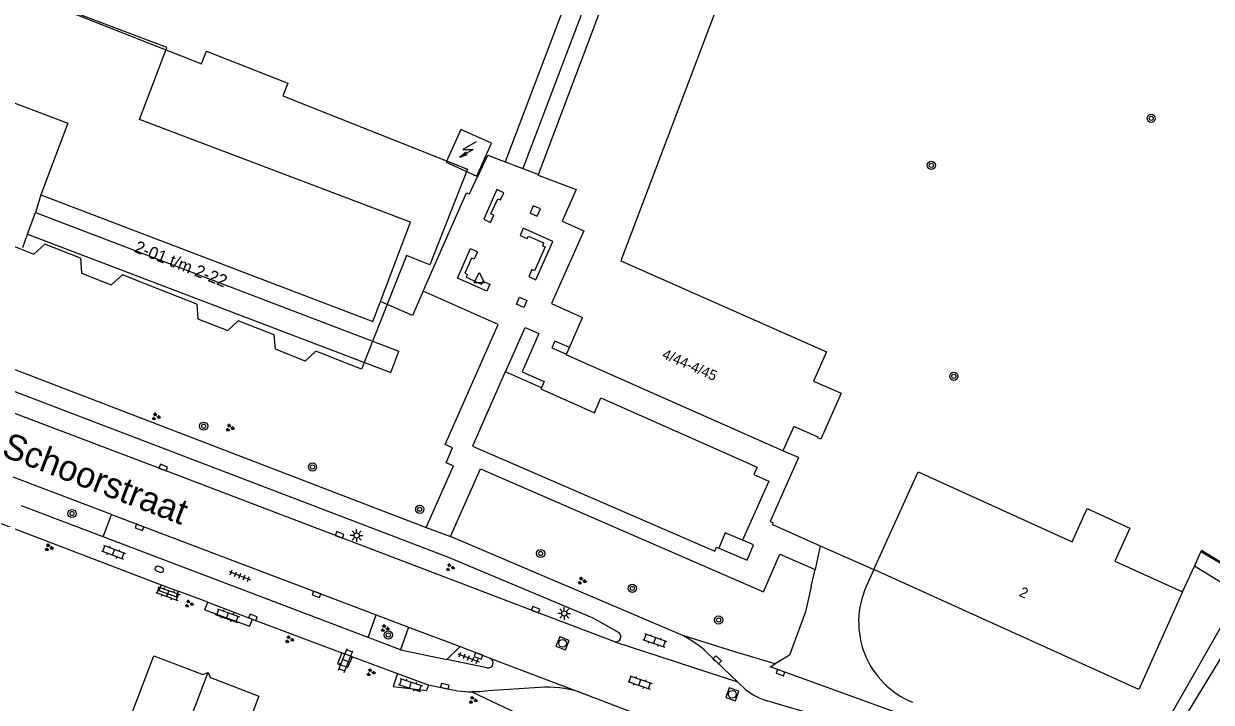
# Model space of a CAD drawing. Extents: x 136000 to 141014, y 402000 to 403500.
# Drawn here: x 137842.2 to 137958.3, y 402614.1 to 402680.4 of the extents above; entities that cross this region are included whole.
import ezdxf

# ---------------------------------------------------------------- set-up
doc = ezdxf.new("R2010")
doc.units = 0
for name, color, linetype in [('gg-afsc-hekwerk', 7, 'Continuous'), ('gg-afsc-muur', 7, 'Continuous'), ('gg-anno-huisnummerreeks BGT', 7, 'Continuous'), ('gg-anno-openbare ruimte label', 7, 'Continuous'), ('gg-bbg-bijgebouw', 7, 'Continuous'), ('gg-bbg-hoofdgebouw', 7, 'Continuous'), ('gg-bbg-lage trafo', 7, 'Continuous'), ('gg-bbg-tussenscheiding', 7, 'Continuous'), ('gg-knt-verharding', 7, 'Continuous'), ('gg-knt-verharding nz', 7, 'Continuous'), ('gt-anno-plantopografie huisnummer', 7, 'Continuous'), ('gt-bbg-plantopografie pand', 7, 'Continuous'), ('gt-grn-vlakafsluiter', 7, 'Continuous'), ('gt-grn-weggrens', 7, 'Continuous'), ('gt-symb-boom', 7, 'Continuous'), ('gt-symb-brandkraan', 7, 'Continuous'), ('gt-symb-groenvak', 7, 'Continuous'), ('gt-symb-klinker verharding', 7, 'Continuous'), ('gt-symb-kolk', 7, 'Continuous'), ('gt-symb-lichtmast', 7, 'Continuous'), ('gt-symb-rioolschacht', 7, 'Continuous'), ('gt-symb-tegel verharding', 7, 'Continuous'), ('gt-symb-trafo symbool', 7, 'Continuous'), ('gt-symb-waterafsluiter', 7, 'Continuous')]:
    doc.layers.add(name, color=color, linetype=linetype)

# ---------------------------------------------------------------- blocks, each defined once
blk = doc.blocks.new('gt0-BOOM')
at = {"layer": 'gt-symb-boom'}
for radius in [0.4, 0.2]:
    blk.add_circle((0, 0), radius, dxfattribs=at)
blk = doc.blocks.new('gt0-HSP')
at = {"layer": 'gt-symb-trafo symbool'}
for points in [[(0.77, 0.75), (-0.53, 0), (0.47, 0), (-0.83, -0.75)], [(-0.22, -0.24), (-0.83, -0.75), (-0.08, -0.48)]]:
    blk.add_lwpolyline(points, dxfattribs=at)
blk = doc.blocks.new('gt0-WAFSL')
at = {"layer": 'gt-symb-waterafsluiter'}
for p, q in [((-0.5, -0.33), (0, 0.67)), ((0, 0.67), (0.5, -0.33)), ((0.5, -0.33), (-0.5, -0.33))]:
    blk.add_line(p, q, dxfattribs=at)
blk = doc.blocks.new('gt0-KOLK')
at = {"layer": 'gt-symb-kolk'}
blk.add_lwpolyline([(0, 0), (0.38, 0), (0.38, 0.4), (-0.37, 0.4), (-0.37, 0), (0, 0)], dxfattribs=at)
blk = doc.blocks.new('gt0-GRVAK')
at = {"layer": 'gt-symb-groenvak'}
for p, q in [((-0.11, 0.19), (-0.23, 0.24)), ((-0.18, 0.15), (0.09, 0.15)), ((-0.09, 0.21), (-0.16, 0.32)), ((-0.05, 0.21), (-0.05, 0.39)), ((0, 0.21), (0.06, 0.32)), ((0.02, 0.19), (0.13, 0.24)), ((0.26, -0.05), (0.2, 0.06)), ((0.31, -0.05), (0.31, 0.13)), ((0.35, -0.05), (0.41, 0.06)), ((-0.24, -0.23), (-0.36, -0.18)), ((-0.32, -0.26), (-0.05, -0.26)), ((-0.23, -0.21), (-0.29, -0.1)), ((-0.18, -0.2), (-0.18, -0.02)), ((-0.14, -0.21), (-0.07, -0.1)), ((-0.12, -0.23), (0, -0.18)), ((0.24, -0.07), (0.12, -0.02)), ((0.17, -0.11), (0.44, -0.11)), ((0.37, -0.07), (0.49, -0.02))]:
    blk.add_line(p, q, dxfattribs=at)
blk = doc.blocks.new('gt0-KL1')
at = {"layer": 'gt-symb-klinker verharding'}
for p, q in [((-1.15, 0.3), (1.15, 0.3)), ((-1, -0.3), (-1, 0.3)), ((-0.5, 0.3), (-0.5, 0.45)), ((0, -0.3), (0, 0.3)), ((0.5, 0.3), (0.5, 0.45)), ((1, -0.3), (1, 0.3)), ((-1.15, -0.3), (1.15, -0.3)), ((-0.5, -0.45), (-0.5, -0.3)), ((0.5, -0.45), (0.5, -0.3))]:
    blk.add_line(p, q, dxfattribs=at)
blk = doc.blocks.new('gt0-TEG1')
at = {"layer": 'gt-symb-tegel verharding'}
for p, q in [((-1.12, 0), (1.12, 0)), ((-0.9, -0.25), (-0.9, 0.25)), ((-0.45, -0.25), (-0.45, 0.25)), ((0, -0.25), (0, 0.25)), ((0.45, -0.25), (0.45, 0.25)), ((0.9, -0.25), (0.9, 0.25))]:
    blk.add_line(p, q, dxfattribs=at)
blk = doc.blocks.new('gt0-BR')
at = {"layer": 'gt-symb-brandkraan'}
for centre, radius, start, end in [((-0.24, 0), 0.206, 107.5669, 252.4331), ((0.6, -2.66), 3, 106.892, 107.5669), ((0, -0.69), 0.938, 73.108, 106.892), ((-0.6, -2.66), 3, 72.4331, 73.108), ((0.24, 0), 0.206, 287.567, 72.4331), ((0.6, 2.66), 3, 252.4331, 253.108), ((0, 0.69), 0.938, 253.108, 286.8921), ((-0.6, 2.66), 3, 286.8921, 287.567)]:
    blk.add_arc(centre, radius, start, end, dxfattribs=at)
blk = doc.blocks.new('gt0-LMAST')
at = {"layer": 'gt-symb-lichtmast'}
for p, q in [((-0.18, 0.17), (-0.45, 0.44)), ((0, 0.25), (0, 0.62)), ((0.17, 0.17), (0.44, 0.44)), ((-0.25, 0), (-0.63, 0)), ((-0.18, -0.18), (-0.45, -0.45)), ((0, -0.25), (0, -0.63)), ((0.44, -0.45), (0.17, -0.18)), ((0.25, 0), (0.62, 0))]:
    blk.add_line(p, q, dxfattribs=at)
blk.add_circle((0, 0), 0.25, dxfattribs=at)
blk = doc.blocks.new('gt0-RS')
at = {"layer": 'gt-symb-rioolschacht'}
blk.add_lwpolyline([(-0.5, -0.5), (0.5, -0.5), (0.5, 0.5), (-0.5, 0.5)], close=True, dxfattribs=at)
blk.add_circle((0, 0), 0.375, dxfattribs=at)

msp = doc.modelspace()

# ---------------------------------------------------------------- linework, layer by layer
at = {"layer": 'gg-afsc-hekwerk'}
msp.add_lwpolyline([(137990.44, 402673.96), (137961.64, 402626.3), (137957.37, 402628.91)], dxfattribs=at)
at = {"layer": 'gg-afsc-muur'}
for p, q in [((137956.68, 402627.39), (137957.32, 402628.79)), ((137957.32, 402628.79), (137957.37, 402628.91)), ((137955.53, 402624.86), (137956.68, 402627.39)), ((137961.1, 402624.65), (137956.68, 402627.39)), ((137925.35, 402627.04), (137924.61, 402625.39)), ((137951.84, 402608.46), (137961.1, 402624.65))]:
    msp.add_line(p, q, dxfattribs=at)
msp.add_arc((137932.31, 402621.92), 8.45, 155.7292, 247.9261, dxfattribs=at)
at = {"layer": 'gg-bbg-bijgebouw'}
for points in [[(137883.55, 402666.85), (137886.53, 402665.49), (137887.98, 402668.7), (137884.99, 402670.06), (137883.55, 402666.85)], [(137851.53, 402609.67), (137854.97, 402618.63), (137859.75, 402616.79), (137860.25, 402617)]]:
    msp.add_lwpolyline(points, dxfattribs=at)
at = {"layer": 'gg-bbg-hoofdgebouw'}
for p, q in [((137892.52, 402665.59), (137892.55, 402665.66)), ((137892.52, 402665.59), (137896.25, 402664.17)), ((137877.11, 402653.24), (137880.07, 402660.99)), ((137894.56, 402652.71), (137896.88, 402651.68)), ((137895.59, 402648.76), (137896.88, 402651.68)), ((137895.29, 402648.1), (137895.59, 402648.76))]:
    msp.add_line(p, q, dxfattribs=at)
for points in [[(137880.07, 402660.99), (137853.57, 402671.03), (137856.23, 402678.07), (137826.9, 402689.16), (137829.55, 402696.12), (137795.48, 402709.08), (137795.68, 402709.6), (137795.05, 402709.83), (137805.34, 402737.17)], [(137711.67, 402729.74), (137739.8, 402719), (137739.15, 402717.27), (137742.62, 402715.96), (137743.27, 402717.69), (137760.01, 402711.34), (137759.35, 402709.61), (137762.3, 402708.49), (137760.48, 402703.76), (137765.7, 402701.8), (137767.41, 402706.54), (137770.41, 402705.43), (137771.06, 402707.16), (137787.83, 402700.83), (137787.16, 402699.11), (137790.63, 402697.76), (137791.29, 402699.49), (137820.04, 402688.72), (137817.37, 402681.71), (137846.57, 402670.68), (137843.91, 402663.65)], [(137892.55, 402665.66), (137900.7, 402687.29), (137903.14, 402686.37), (137903.99, 402688.68), (137908.52, 402686.96), (137907.65, 402684.66), (137910.58, 402683.55)], [(137910.58, 402683.55), (137900.63, 402657.21), (137920.73, 402648.31)], [(137843.91, 402663.65), (137876.38, 402651.3), (137877.11, 402653.24)], [(137896.25, 402664.17), (137894.89, 402661.1), (137895.12, 402660.99)], [(137895.12, 402660.99), (137897, 402660.16), (137893.83, 402653.03), (137894.56, 402652.71)], [(137920.73, 402648.31), (137919.46, 402645.45), (137922.14, 402644.27), (137920.16, 402639.78), (137919.86, 402639.91), (137919.89, 402639.99), (137917.51, 402641.04), (137916.46, 402638.66)], [(137916.46, 402638.66), (137895.26, 402648.03), (137895.29, 402648.1)], [(137925.35, 402627.04), (137929.69, 402636.6), (137944.72, 402629.77), (137946.19, 402633), (137950.38, 402631.1), (137948.91, 402627.87), (137955.53, 402624.86)], [(137955.53, 402624.86), (137951.24, 402615.33), (137925.35, 402627.04)], [(137860.25, 402617), (137860.49, 402616.5), (137865.24, 402614.67), (137864.12, 402611.75), (137866.39, 402610.92)]]:
    msp.add_lwpolyline(points, dxfattribs=at)
at = {"layer": 'gg-bbg-lage trafo'}
for points in [[(137912.51, 402629.91), (137910.81, 402630.63), (137910.19, 402629.15)], [(137910.19, 402629.15), (137912.95, 402627.98), (137913.57, 402629.47), (137912.51, 402629.91)]]:
    msp.add_lwpolyline(points, dxfattribs=at)
at = {"layer": 'gg-bbg-tussenscheiding'}
msp.add_line((137860.25, 402617), (137856.69, 402607.69), dxfattribs=at)
at = {"layer": 'gg-knt-verharding'}
for p, q in [((137891.02, 402666.24), (137892.55, 402665.66)), ((137843.91, 402663.65), (137843.39, 402661.92)), ((137843.39, 402661.92), (137878.92, 402648.4)), ((137842.17, 402658.53), (137842.62, 402659.82)), ((137842.62, 402659.82), (137878.12, 402646.3)), ((137815.26, 402656.59), (137881.6, 402631.17)), ((137878.12, 402646.3), (137878.92, 402648.4)), ((137892.86, 402644.82), (137889.34, 402646.36)), ((137850.83, 402632.44), (137841.23, 402636.08)), ((137830.26, 402635.26), (137855.69, 402625.57)), ((137850.01, 402630.25), (137842.03, 402633.27)), ((137850.01, 402630.25), (137850.83, 402632.44)), ((137850.83, 402632.44), (137876.71, 402622.62)), ((137915.43, 402631.45), (137920.11, 402629.37)), ((137875.92, 402620.4), (137850.01, 402630.25)), ((137906.69, 402620.61), (137883.98, 402630.28)), ((137920.11, 402629.37), (137925.35, 402627.04)), ((137963.37, 402625.22), (137957.32, 402628.79)), ((137919.22, 402625.38), (137919.6, 402627.06)), ((137855.69, 402625.57), (137855.46, 402625)), ((137855.69, 402625.57), (137857.34, 402624.93)), ((137857.34, 402624.93), (137857.14, 402624.37)), ((137860.23, 402623.85), (137857.34, 402624.93)), ((137859.96, 402623.1), (137860.23, 402623.85)), ((137860.23, 402623.85), (137864.57, 402622.19)), ((137864.57, 402622.19), (137864.32, 402621.52)), ((137864.57, 402622.19), (137873.33, 402618.92)), ((137875.92, 402620.4), (137876.71, 402622.62)), ((137876.71, 402622.62), (137879.87, 402621.43)), ((137879.09, 402619.22), (137875.92, 402620.4)), ((137879.87, 402621.43), (137879.09, 402619.22)), ((137879.87, 402621.43), (137884.92, 402619.52)), ((137883.59, 402618.26), (137884.92, 402619.52)), ((137873.33, 402618.92), (137872.93, 402617.83)), ((137874.39, 402618.51), (137873.33, 402618.92)), ((137873.93, 402617.51), (137874.39, 402618.51)), ((137874.39, 402618.51), (137878.77, 402616.88)), ((137887.53, 402617.45), (137883.59, 402618.26)), ((137912.01, 402616.09), (137909.89, 402618.09)), ((137878.77, 402616.88), (137878.35, 402615.61)), ((137881.82, 402615.8), (137881.61, 402615.24)), ((137881.82, 402615.8), (137883.36, 402615.46)), ((137912.83, 402615.31), (137912.01, 402616.09)), ((137886.05, 402615.1), (137893.99, 402611.35))]:
    msp.add_line(p, q, dxfattribs=at)
for points in [[(137919.05, 402718.8), (137909.2, 402707.35), (137894.26, 402696.18), (137892.52, 402695.8), (137894.83, 402681.39), (137889.3, 402666.9)], [(137920.71, 402717.75), (137910.61, 402706.15), (137895.75, 402694.91), (137894.79, 402693.56), (137896.71, 402681.16), (137891.02, 402666.24)], [(137881.29, 402654.25), (137885.52, 402663.87), (137885.82, 402663.76), (137886.6, 402665.46), (137886.65, 402665.44), (137887.62, 402667.54), (137889.3, 402666.9)], [(137889.18, 402663.86), (137888.49, 402664.18), (137887.21, 402661.27), (137887.88, 402660.97), (137888.2, 402661.67), (137887.92, 402661.8), (137888.6, 402663.27), (137888.86, 402663.18), (137889.18, 402663.86)], [(137892.06, 402662.59), (137891.75, 402661.88), (137892.45, 402661.57), (137892.77, 402662.28), (137892.06, 402662.59)], [(137891.08, 402660.39), (137890.76, 402659.69), (137891.46, 402659.38), (137891.59, 402659.64), (137893.07, 402658.96), (137892.97, 402658.69), (137893.23, 402658.57), (137892.19, 402656.25), (137891.92, 402656.38), (137891.61, 402655.67), (137892.32, 402655.37), (137893.97, 402659.09), (137891.08, 402660.39)], [(137887.82, 402654.92), (137887.52, 402654.24), (137884.64, 402655.51), (137885.93, 402658.41), (137886.61, 402658.09), (137886.28, 402657.39), (137886.03, 402657.49), (137885.38, 402656.01), (137885.63, 402655.89), (137885.5, 402655.63), (137887.01, 402654.95), (137887.14, 402655.22), (137887.82, 402654.92)], [(137881.6, 402631.17), (137884.25, 402637.18), (137883.53, 402637.48), (137884.16, 402638.95), (137883.44, 402639.26), (137888.61, 402650.98), (137881.29, 402654.25)], [(137890.71, 402653.65), (137891.41, 402653.33), (137891.12, 402652.64), (137890.41, 402652.97), (137890.71, 402653.65)], [(137900.45, 402620.88), (137897.9, 402622.3), (137883.7, 402628.26), (137824.65, 402650.8)], [(137889.34, 402646.36), (137891.26, 402650.69), (137892.6, 402650.1), (137890.96, 402646.38), (137893.12, 402645.42), (137892.86, 402644.82)], [(137895.59, 402648.76), (137894.16, 402649.36), (137893.88, 402648.72), (137895.29, 402648.1)], [(137900.02, 402620), (137892.21, 402622.95), (137855.81, 402636.83), (137835.67, 402644.45), (137829.85, 402646.72)], [(137889.34, 402646.36), (137889.32, 402646.37), (137886.13, 402639.11), (137909.81, 402628.86), (137909.97, 402629.24), (137910.19, 402629.15)], [(137892.86, 402644.82), (137892.81, 402644.72), (137898.05, 402642.36), (137898.67, 402643.83), (137913.93, 402637.07), (137913.62, 402636.35), (137915.07, 402635.7), (137912.51, 402629.91)], [(137917.98, 402637.99), (137915.22, 402631.74), (137915.48, 402631.64), (137915.43, 402631.45)], [(137883.98, 402630.28), (137886.91, 402636.9), (137914.57, 402624.89), (137916.17, 402628.54), (137919.6, 402627.06)], [(137919.22, 402625.38), (137918.67, 402622.93), (137917.11, 402618.68), (137915.71, 402617.85)], [(137951.84, 402608.46), (137953.62, 402609.1), (137962.53, 402623.75)], [(137915.71, 402617.85), (137911.77, 402619.02), (137906.69, 402620.61)], [(137884.92, 402619.52), (137886.77, 402618.81), (137887.82, 402618.39)], [(137928.6, 402612.69), (137915.22, 402617.55), (137915.71, 402617.85)], [(137878.77, 402616.88), (137881.53, 402615.87), (137881.82, 402615.8)], [(137892.65, 402615.53), (137887.65, 402615.19), (137886.85, 402615.11), (137886.05, 402615.1)], [(137896.52, 402615.1), (137924.24, 402604.56), (137929.77, 402602.38), (137934.4, 402600.36)], [(137937.54, 402607.39), (137920.47, 402612.58), (137914.9, 402614.24)]]:
    msp.add_lwpolyline(points, dxfattribs=at)
for centre, radius, start, end in [((137900.13, 402620.49), 0.502, 257.6436, 51.0617), ((137900.84, 402609.89), 12.21, 42.1908, 61.4031), ((137887.64, 402617.93), 0.497, 257.5264, 68.5656), ((137886.34, 402627.35), 12.25, 255.9308, 268.6228), ((137893.5, 402605.34), 10.22, 72.7687, 94.7264), ((137916.74, 402620.35), 6.38, 232.1812, 253.2605)]:
    msp.add_arc(centre, radius, start, end, dxfattribs=at)
at = {"layer": 'gg-knt-verharding nz'}
for p, q in [((137881.6, 402631.17), (137883.98, 402630.28)), ((137900.02, 402620), (137912.01, 402616.09)), ((137887.82, 402618.39), (137896.52, 402615.1))]:
    msp.add_line(p, q, dxfattribs=at)
at = {"layer": 'gt-bbg-plantopografie pand'}
for p, q in [((137847.79, 402657.47), (137844.32, 402658.84)), ((137855.53, 402654.41), (137851.9, 402655.84)), ((137859.16, 402652.97), (137855.53, 402654.41))]:
    msp.add_line(p, q, dxfattribs=at)
for points in [[(137841.56, 402683.61), (137859.63, 402676.46), (137860.12, 402677.71), (137868.06, 402674.57), (137867.56, 402673.32), (137885.64, 402666.16), (137881.94, 402656.82), (137879.65, 402657.72), (137875.26, 402646.62), (137870.79, 402648.4), (137869.76, 402647.42), (137866.85, 402648.58), (137866.74, 402649.97), (137863.22, 402651.36)], [(137840.2, 402660.48), (137840.31, 402659.03), (137843.23, 402657.87), (137844.32, 402658.84)], [(137847.79, 402657.47), (137847.89, 402656.02), (137850.81, 402654.86), (137851.9, 402655.84)], [(137859.16, 402652.97), (137859.27, 402651.56), (137862.2, 402650.4), (137863.22, 402651.36)]]:
    msp.add_lwpolyline(points, dxfattribs=at)
at = {"layer": 'gt-grn-vlakafsluiter'}
for p, q in [((137917.98, 402637.99), (137916.46, 402638.66)), ((137855.46, 402625), (137857.14, 402624.37)), ((137859.96, 402623.1), (137864.32, 402621.52)), ((137872.93, 402617.83), (137873.93, 402617.51)), ((137878.35, 402615.61), (137881.61, 402615.24))]:
    msp.add_line(p, q, dxfattribs=at)
msp.add_lwpolyline([(137881.29, 402654.25), (137880.24, 402651.86), (137877.11, 402653.24)], dxfattribs=at)
at = {"layer": 'gt-grn-weggrens'}
for p, q in [((137889.3, 402666.9), (137891.02, 402666.24)), ((137842.62, 402659.82), (137843.39, 402661.92)), ((137920.11, 402629.37), (137919.6, 402627.06)), ((137879.09, 402619.22), (137883.59, 402618.26))]:
    msp.add_line(p, q, dxfattribs=at)

# ---------------------------------------------------------------- block references
at = {"layer": 'gt-symb-boom'}
for p in [(137952.46, 402671.14), (137930.97, 402666.54), (137933.17, 402645.93), (137859.83, 402641.06), (137870.47, 402637.07), (137880.96, 402632.94), (137846.96, 402632.53), (137892.78, 402628.62), (137901.74, 402625.21), (137910.17, 402622.12), (137877.89, 402620.66)]:
    msp.add_blockref('gt0-BOOM', p, dxfattribs=at)
at = {"layer": 'gt-symb-brandkraan', "rotation": -19.70395158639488}
msp.add_blockref('gt0-BR', (137855.5, 402627.08), dxfattribs=at)
at = {"layer": 'gt-symb-groenvak'}
for p in [(137855.15, 402641.99), (137862.39, 402640.89), (137844.69, 402629.2), (137883.91, 402627.25), (137896.79, 402625.94), (137858.4, 402623.7), (137877.53, 402621.31), (137868.2, 402620.22), (137876.16, 402617), (137886.14, 402614.29)]:
    msp.add_blockref('gt0-GRVAK', p, dxfattribs=at)
at = {"layer": 'gt-symb-klinker verharding'}
for p, rotation in [((137851.02, 402628.74), -20.60969293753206), ((137856.34, 402624.7), -19.576725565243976), ((137862.16, 402622.55), -19.576725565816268), ((137903.93, 402620.13), -19.21431186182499), ((137873.72, 402618.16), 68.028289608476), ((137880.04, 402615.76), -17.945563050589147), ((137902.48, 402616.02), -19.21431186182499)]:
    msp.add_blockref('gt0-KL1', p, dxfattribs=dict(at, rotation=rotation))
at = {"layer": 'gt-symb-kolk'}
for p, rotation in [((137855.81, 402636.83), -20.737148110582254), ((137853.64, 402631.37), 159.2092747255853), ((137873.05, 402630.25), -20.91820498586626), ((137870.94, 402624.81), 159.2092747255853), ((137892.21, 402622.95), -20.844264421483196), ((137864.57, 402622.19), -20.918204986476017), ((137886.77, 402618.81), 159.26285188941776), ((137909.89, 402618.09), -43.3164899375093), ((137916.15, 402616.79), -19.630702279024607), ((137883.36, 402615.46), -13.01457605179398)]:
    msp.add_blockref('gt0-KOLK', p, dxfattribs=dict(at, rotation=rotation))
at = {"layer": 'gt-symb-lichtmast'}
for p in [(137874.79, 402630.38), (137895.09, 402622.76)]:
    msp.add_blockref('gt0-LMAST', p, dxfattribs=at)
at = {"layer": 'gt-symb-rioolschacht'}
for p, rotation in [((137894.92, 402619.84), -21.354377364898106), ((137911.51, 402614.86), 160.0899712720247)]:
    msp.add_blockref('gt0-RS', p, dxfattribs=dict(at, rotation=rotation))
at = {"layer": 'gt-symb-tegel verharding'}
for p, rotation in [((137863.37, 402626.45), -20.918204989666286), ((137885.73, 402618.42), -20.918204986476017)]:
    msp.add_blockref('gt0-TEG1', p, dxfattribs=dict(at, rotation=rotation))
at = {"layer": 'gt-symb-trafo symbool'}
msp.add_blockref('gt0-HSP', (137885.7, 402668.08), dxfattribs=at)
at = {"layer": 'gt-symb-waterafsluiter'}
msp.add_blockref('gt0-WAFSL', (137886.78, 402655.4), dxfattribs=at)

# ---------------------------------------------------------------- texts
at = {"layer": 'gg-anno-huisnummerreeks BGT'}
for s, rotation, p in [('4/44-4/45', 336.2, (137904.57, 402647.74)), ('2', 335.7, (137939.47, 402624.5))]:
    msp.add_text(s, height=1, rotation=rotation, dxfattribs=at).set_placement(p)
at = {"layer": 'gg-anno-openbare ruimte label'}
msp.add_text('Schoorstraat', height=2.5, rotation=339, dxfattribs=at).set_placement((137839.97, 402638.19))
at = {"layer": 'gt-anno-plantopografie huisnummer'}
msp.add_text('2-01 t/m 2-22', height=1.2, rotation=338.3964, dxfattribs=at).set_placement((137852.97, 402658.11))

doc.saveas('drawing.dxf')
